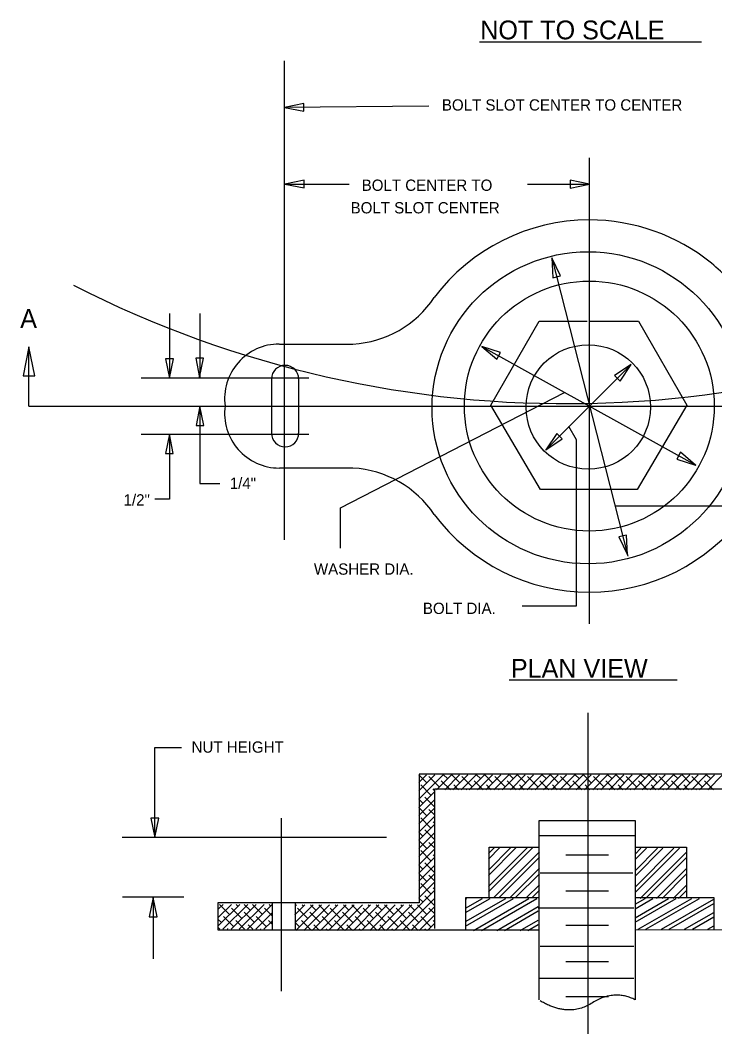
# Model space of a CAD drawing. Extents: x 12.4 to 19.6, y 6 to 16.1.
# Drawn here: x 12.93 to 16.63, y 10.72 to 16.11 of the extents above; entities that cross this region are included whole.
import ezdxf

# ---------------------------------------------------------------- set-up
doc = ezdxf.new("R2010")
doc.units = 0
for name, color, linetype in [('DETL-DIMS', 7, 'Continuous'), ('DETL-LINE', 7, 'Continuous'), ('DETL-NOTE', 7, 'Continuous'), ('DETL-PATT', 7, 'Continuous'), ('DETL-TITL', 7, 'Continuous')]:
    doc.layers.add(name, color=color, linetype=linetype)

msp = doc.modelspace()

# ---------------------------------------------------------------- linework, layer by layer
at = {"layer": 'DETL-DIMS'}
for p, q in [((14.3359, 13.3479), (14.3359, 15.8959)), ((14.3329, 15.6499), (15.1049, 15.6569)), ((15.9589, 12.9019), (15.9589, 15.3799)), ((14.3329, 15.2409), (14.6809, 15.2409)), ((15.6289, 15.2409), (15.9549, 15.2409)), ((15.7599, 14.8479), (16.1629, 13.2619)), ((13.7239, 14.5529), (13.7239, 14.2079)), ((13.8859, 14.5529), (13.8859, 14.2079)), ((15.3869, 14.3769), (16.5259, 13.7449)), ((15.7259, 13.8259), (16.1789, 14.2789)), ((14.4659, 14.2079), (13.5739, 14.2079)), ((14.6349, 13.5189), (15.8269, 14.1329)), ((13.8859, 14.0599), (13.8859, 13.6489)), ((15.8899, 13.8799), (15.8499, 13.9519)), ((14.4659, 13.9079), (13.5739, 13.9079)), ((13.7239, 13.9079), (13.7239, 13.5639)), ((15.8899, 12.9969), (15.8899, 13.8799)), ((13.8859, 13.6489), (13.9919, 13.6489)), ((13.7239, 13.5639), (13.6459, 13.5639)), ((14.6349, 13.3049), (14.6349, 13.5189)), ((16.9369, 13.5269), (16.0979, 13.5269)), ((15.6019, 12.9969), (15.8899, 12.9969)), ((15.9509, 12.4279), (15.9509, 10.7209)), ((13.6449, 12.2419), (13.6449, 11.7649)), ((13.7879, 12.2419), (13.6449, 12.2419)), ((14.3189, 11.8669), (14.3189, 10.9479)), ((14.8799, 11.7649), (13.4719, 11.7649)), ((13.8009, 11.4469), (13.4739, 11.4469)), ((13.6369, 11.4469), (13.6369, 11.1199))]:
    msp.add_line(p, q, dxfattribs=at)
for points in [[(14.3359, 15.6489), (14.4389, 15.6289), (14.4389, 15.6699)], [(14.3379, 15.2409), (14.4409, 15.2209), (14.4409, 15.2619)], [(15.9599, 15.2409), (15.8559, 15.2609), (15.8559, 15.2199)], [(15.7599, 14.8479), (15.7649, 14.7429), (15.8049, 14.7529)], [(12.9759, 14.3759), (12.9459, 14.2209), (13.0079, 14.2209)], [(15.3859, 14.3769), (15.4659, 14.3089), (15.4859, 14.3449)], [(13.7249, 14.2079), (13.7459, 14.3119), (13.7039, 14.3119)], [(13.8839, 14.2119), (13.9049, 14.3149), (13.8639, 14.3149)], [(16.1809, 14.2809), (16.0929, 14.2219), (16.1219, 14.1929)], [(13.8859, 14.0599), (13.8659, 13.9569), (13.9069, 13.9569)], [(15.7269, 13.8279), (15.8149, 13.8859), (15.7859, 13.9149)], [(13.7239, 13.9099), (13.7029, 13.8069), (13.7439, 13.8069)], [(16.5239, 13.7459), (16.4439, 13.8139), (16.4239, 13.7779)], [(16.1609, 13.2689), (16.1559, 13.3739), (16.1159, 13.3639)], [(13.6469, 11.7649), (13.6669, 11.8679), (13.6259, 11.8679)], [(13.6379, 11.4449), (13.6169, 11.3419), (13.6589, 11.3419)]]:
    msp.add_lwpolyline(points, close=True, dxfattribs=at)
for points in [[(12.9759, 14.0599), (12.9759, 14.3759)], [(12.9759, 14.0599), (18.9259, 14.0599)]]:
    msp.add_lwpolyline(points, dxfattribs=at)
msp.add_arc((15.8374, 19.8541), 5.7813, 243.01004, 299.38525, dxfattribs=at)
at = {"layer": 'DETL-LINE'}
for p, q in [((15.6919, 11.7759), (16.2069, 11.7759)), ((15.8329, 11.6729), (16.0599, 11.6729)), ((15.6969, 11.5769), (16.1899, 11.5769)), ((15.8329, 11.4809), (16.0599, 11.4809)), ((15.6859, 11.3899), (16.1959, 11.3899)), ((15.8329, 11.2989), (16.0599, 11.2989)), ((15.6969, 11.1859), (16.1959, 11.1859)), ((15.8329, 11.1059), (16.0599, 11.1059)), ((15.6919, 11.0159), (16.1959, 11.0159)), ((15.8329, 10.9189), (16.0599, 10.9189))]:
    msp.add_line(p, q, dxfattribs=at)
for points in [[(15.9639, 14.5109), (16.2209, 14.5109), (16.4769, 14.0649), (16.2129, 13.6169), (15.9559, 13.6169), (15.6979, 13.6169), (15.4349, 14.0649), (15.6909, 14.5109), (15.9479, 14.5109)], [(14.3089, 14.3899), (14.7009, 14.3899)], [(14.2679, 14.2049), (14.2679, 14.0599), (14.2679, 13.9159)], [(14.4119, 14.0599), (14.4119, 14.2049)], [(14.4119, 13.9159), (14.4119, 14.0599)], [(14.7009, 13.7299), (14.3089, 13.7299)], [(16.2019, 11.2739), (17.8999, 11.2749), (17.8999, 11.4279), (16.8679, 11.4279), (16.8679, 12.1019), (15.0529, 12.1019), (15.0529, 11.4179), (13.9819, 11.4179), (13.9809, 11.2729)], [(15.1359, 11.2799), (15.1359, 12.0229), (16.7859, 12.0229), (16.7859, 11.2799)], [(15.6919, 11.2709), (15.6919, 11.8549), (16.2019, 11.8549), (16.2019, 11.2709)], [(15.4249, 11.4449), (15.4249, 11.7129), (15.6899, 11.7129)], [(16.2079, 11.7129), (16.4759, 11.7129), (16.4759, 11.4449)], [(15.3009, 11.2739), (15.3009, 11.4449), (15.6899, 11.4449)], [(16.2079, 11.4449), (16.6209, 11.4449), (16.6209, 11.2739)], [(14.2699, 11.4179), (14.2699, 11.2729)], [(14.3929, 11.4179), (14.3929, 11.2729)], [(13.9809, 11.2729), (15.6919, 11.2739)], [(15.6919, 10.9019), (15.6919, 11.2769)], [(16.2019, 11.2709), (16.2019, 10.9019)]]:
    msp.add_lwpolyline(points, dxfattribs=at)
for centre, radius in [((15.952, 14.0508), 0.83), ((15.9586, 14.0601), 0.665), ((15.9532, 14.055), 0.3312)]:
    msp.add_circle(centre, radius, dxfattribs=at)
for centre, radius, start, end in [((15.9586, 14.0188), 1.0313, 90, 143.1301), ((15.9586, 14.0188), 1.0313, 50.9692, 90), ((15.9586, 14.0188), 1.0313, 36.8699, 50.9692), ((14.6692, 14.9475), 0.5583, 273.2108, 326.279), ((14.3086, 14.0987), 0.2913, 90, 187.6282), ((14.3395, 14.2044), 0.0722, 0, 180), ((14.3086, 14.0214), 0.2913, 172.3718, 270), ((14.3395, 13.9157), 0.0722, 180, 0), ((14.6692, 13.1726), 0.5583, 33.721, 86.7892), ((15.9586, 14.1013), 1.0313, 216.8699, 270), ((15.9586, 14.1013), 1.0313, 270, 323.1301)]:
    msp.add_arc(centre, radius, start, end, dxfattribs=at)
msp.add_open_spline([(16.2019, 10.9019), (16.0879, 10.9589), (15.8499, 10.8059), (15.6969, 10.8959)], degree=2, dxfattribs=at)
at = {"layer": 'DETL-PATT'}
for p, q in [((15.0509, 11.9689), (15.1809, 12.0989)), ((15.0509, 12.0129), (15.1369, 12.0989)), ((15.0509, 12.0569), (15.0929, 12.0989)), ((15.0939, 12.0559), (15.0519, 12.0989)), ((15.1599, 12.0339), (15.1049, 12.0889)), ((15.1449, 12.0189), (15.2249, 12.0989)), ((15.2039, 12.0779), (15.1829, 12.0989)), ((15.1889, 12.0189), (15.2679, 12.0989)), ((15.2689, 12.0559), (15.2269, 12.0989)), ((15.2329, 12.0189), (15.3119, 12.0989)), ((15.2759, 12.0189), (15.3559, 12.0989)), ((15.3349, 12.0339), (15.2799, 12.0889)), ((15.3199, 12.0189), (15.3999, 12.0989)), ((15.3789, 12.0779), (15.3579, 12.0989)), ((15.3639, 12.0189), (15.4429, 12.0989)), ((15.4439, 12.0559), (15.4019, 12.0989)), ((15.4079, 12.0189), (15.4869, 12.0989)), ((15.4509, 12.0189), (15.5309, 12.0989)), ((15.5099, 12.0339), (15.4549, 12.0889)), ((15.4949, 12.0189), (15.5749, 12.0989)), ((15.5539, 12.0779), (15.5329, 12.0989)), ((15.5389, 12.0189), (15.6179, 12.0989)), ((15.6189, 12.0559), (15.5769, 12.0989)), ((15.5829, 12.0189), (15.6619, 12.0989)), ((15.6269, 12.0189), (15.7059, 12.0989)), ((15.6849, 12.0339), (15.6299, 12.0889)), ((15.6699, 12.0189), (15.7499, 12.0989)), ((15.7289, 12.0779), (15.7079, 12.0989)), ((15.7139, 12.0189), (15.7929, 12.0989)), ((15.7939, 12.0559), (15.7519, 12.0989)), ((15.7579, 12.0189), (15.8369, 12.0989)), ((15.8019, 12.0189), (15.8809, 12.0989)), ((15.8599, 12.0339), (15.8049, 12.0889)), ((15.8449, 12.0189), (15.9249, 12.0989)), ((15.9039, 12.0779), (15.8829, 12.0989)), ((15.8889, 12.0189), (15.9679, 12.0989)), ((15.9689, 12.0559), (15.9269, 12.0989)), ((15.9329, 12.0189), (16.0119, 12.0989)), ((15.9769, 12.0189), (16.0559, 12.0989)), ((16.0349, 12.0339), (15.9799, 12.0889)), ((16.0199, 12.0189), (16.0999, 12.0989)), ((16.0789, 12.0779), (16.0579, 12.0989)), ((16.0639, 12.0189), (16.1429, 12.0989)), ((16.1439, 12.0559), (16.1019, 12.0989)), ((16.1079, 12.0189), (16.1869, 12.0989)), ((16.1519, 12.0189), (16.2309, 12.0989)), ((16.2099, 12.0339), (16.1549, 12.0889)), ((16.1949, 12.0189), (16.2749, 12.0989)), ((16.2539, 12.0779), (16.2329, 12.0989)), ((16.2389, 12.0189), (16.3179, 12.0989)), ((16.3189, 12.0559), (16.2769, 12.0989)), ((16.2829, 12.0189), (16.3619, 12.0989)), ((16.3269, 12.0189), (16.4059, 12.0989)), ((16.3849, 12.0339), (16.3299, 12.0889)), ((16.3699, 12.0189), (16.4499, 12.0989)), ((16.4289, 12.0779), (16.4079, 12.0989)), ((16.4139, 12.0189), (16.4929, 12.0989)), ((16.4939, 12.0559), (16.4519, 12.0989)), ((16.4579, 12.0189), (16.5369, 12.0989)), ((16.5019, 12.0189), (16.5809, 12.0989)), ((16.5599, 12.0339), (16.5049, 12.0889)), ((16.5449, 12.0189), (16.6249, 12.0989)), ((16.6039, 12.0779), (16.5829, 12.0989)), ((16.5889, 12.0189), (16.6679, 12.0989)), ((15.1159, 11.9899), (15.0619, 12.0449)), ((15.2189, 12.0189), (15.1709, 12.0669)), ((15.2619, 12.0189), (15.2369, 12.0449)), ((15.3939, 12.0189), (15.3459, 12.0669)), ((15.4369, 12.0189), (15.4119, 12.0449)), ((15.5689, 12.0189), (15.5209, 12.0669)), ((15.6119, 12.0189), (15.5869, 12.0449)), ((15.7439, 12.0189), (15.6959, 12.0669)), ((15.7869, 12.0189), (15.7619, 12.0449)), ((15.9189, 12.0189), (15.8709, 12.0669)), ((15.9619, 12.0189), (15.9369, 12.0449)), ((16.0939, 12.0189), (16.0459, 12.0669)), ((16.1369, 12.0189), (16.1119, 12.0449)), ((16.2689, 12.0189), (16.2209, 12.0669)), ((16.3119, 12.0189), (16.2869, 12.0449)), ((16.4439, 12.0189), (16.3959, 12.0669)), ((16.4869, 12.0189), (16.4619, 12.0449)), ((16.6189, 12.0189), (16.5709, 12.0669)), ((15.0509, 11.9249), (15.1359, 12.0099)), ((15.1359, 11.9269), (15.0829, 11.9799)), ((15.1359, 12.0139), (15.1269, 12.0229)), ((15.3059, 12.0189), (15.3019, 12.0229)), ((15.4809, 12.0189), (15.4769, 12.0229)), ((15.6559, 12.0189), (15.6519, 12.0229)), ((15.8309, 12.0189), (15.8269, 12.0229)), ((16.0059, 12.0189), (16.0019, 12.0229)), ((16.1809, 12.0189), (16.1769, 12.0229)), ((16.3559, 12.0189), (16.3519, 12.0229)), ((16.5309, 12.0189), (16.5269, 12.0229)), ((15.0719, 11.9469), (15.0509, 11.9679)), ((15.0509, 11.8819), (15.1359, 11.9669)), ((15.0939, 11.8809), (15.0509, 11.9239)), ((15.0509, 11.8379), (15.1359, 11.9229)), ((15.0509, 11.7939), (15.1359, 11.8789)), ((15.1159, 11.8149), (15.0619, 11.8699)), ((15.1359, 11.8829), (15.1049, 11.9139)), ((15.0509, 11.7499), (15.1359, 11.8349)), ((15.1359, 11.8389), (15.1269, 11.8479)), ((15.0719, 11.7719), (15.0509, 11.7929)), ((15.0509, 11.7069), (15.1359, 11.7919)), ((15.1359, 11.7519), (15.0829, 11.8049)), ((15.0939, 11.7059), (15.0509, 11.7489)), ((15.0509, 11.6629), (15.1359, 11.7479)), ((15.0509, 11.6189), (15.1359, 11.7039)), ((15.1359, 11.7079), (15.1049, 11.7389)), ((15.4219, 11.5039), (15.6289, 11.7119)), ((15.4219, 11.5919), (15.5409, 11.7119)), ((15.4219, 11.6799), (15.4539, 11.7119)), ((15.4219, 11.4749), (15.6579, 11.7119)), ((15.4219, 11.5629), (15.5699, 11.7119)), ((15.4219, 11.6499), (15.4829, 11.7119)), ((16.2019, 11.5009), (16.4079, 11.7079)), ((16.2019, 11.5879), (16.3209, 11.7079)), ((16.2019, 11.6759), (16.2329, 11.7079)), ((16.2019, 11.4719), (16.4379, 11.7079)), ((16.2019, 11.5589), (16.3499, 11.7079)), ((16.2019, 11.6469), (16.2629, 11.7079)), ((15.0509, 11.5749), (15.1359, 11.6599)), ((15.1159, 11.6399), (15.0619, 11.6949)), ((15.1359, 11.6639), (15.1269, 11.6729)), ((15.4499, 11.4449), (15.6939, 11.6889)), ((15.4789, 11.4449), (15.6939, 11.6599)), ((16.2289, 11.4409), (16.4739, 11.6849)), ((16.2579, 11.4409), (16.4739, 11.6559)), ((15.0719, 11.5969), (15.0509, 11.6179)), ((15.0509, 11.5319), (15.1359, 11.6169)), ((15.1359, 11.5769), (15.0829, 11.6299)), ((15.5369, 11.4449), (15.6939, 11.6019)), ((16.3169, 11.4409), (16.4739, 11.5979)), ((15.0939, 11.5309), (15.0509, 11.5739)), ((15.0509, 11.4879), (15.1359, 11.5729)), ((15.1359, 11.5329), (15.1049, 11.5639)), ((15.5659, 11.4449), (15.6939, 11.5719)), ((16.3459, 11.4409), (16.4739, 11.5689)), ((14.9219, 11.2709), (15.1359, 11.4849)), ((15.0509, 11.4439), (15.1359, 11.5289)), ((15.1159, 11.4649), (15.0619, 11.5199)), ((15.1359, 11.4889), (15.1269, 11.4979)), ((15.6249, 11.4449), (15.6939, 11.5139)), ((15.6539, 11.4449), (15.6939, 11.4849)), ((16.4039, 11.4409), (16.4739, 11.5099)), ((14.9649, 11.2709), (15.1359, 11.4419)), ((15.0719, 11.4219), (15.0509, 11.4429)), ((15.1359, 11.4019), (15.0829, 11.4549)), ((15.2999, 11.3179), (15.5139, 11.4409)), ((15.2999, 11.3889), (15.3899, 11.4409)), ((15.2999, 11.2939), (15.5549, 11.4409)), ((15.2999, 11.3659), (15.4309, 11.4409)), ((15.2999, 11.4369), (15.3069, 11.4409)), ((15.3429, 11.2709), (15.6369, 11.4409)), ((15.3839, 11.2709), (15.6789, 11.4409)), ((16.2019, 11.3379), (16.3799, 11.4409)), ((16.2019, 11.4099), (16.2559, 11.4409)), ((16.2019, 11.3139), (16.4209, 11.4409)), ((16.2019, 11.3859), (16.2969, 11.4409)), ((16.2189, 11.2769), (16.5039, 11.4409)), ((16.2599, 11.2769), (16.5449, 11.4409)), ((16.3419, 11.2769), (16.6209, 11.4369)), ((16.4339, 11.4409), (16.4739, 11.4809)), ((13.9839, 11.2949), (14.0979, 11.4089)), ((13.9839, 11.3389), (14.0539, 11.4089)), ((13.9839, 11.3829), (14.0099, 11.4089)), ((14.0439, 11.3559), (13.9909, 11.4089)), ((14.0089, 11.2769), (14.1409, 11.4089)), ((14.0519, 11.2769), (14.1849, 11.4089)), ((14.1099, 11.3339), (14.0549, 11.3889)), ((14.0879, 11.3999), (14.0789, 11.4089)), ((14.0959, 11.2769), (14.2289, 11.4089)), ((14.1539, 11.3779), (14.1219, 11.4089)), ((14.1399, 11.2769), (14.2689, 11.4059)), ((14.2189, 11.3559), (14.1659, 11.4089)), ((14.2689, 11.3499), (14.2299, 11.3889)), ((14.2629, 11.3999), (14.2539, 11.4089)), ((14.3939, 11.3119), (14.4889, 11.4069)), ((14.3939, 11.3549), (14.4449, 11.4069)), ((14.3939, 11.3989), (14.4009, 11.4069)), ((14.3969, 11.2709), (14.5329, 11.4069)), ((14.4599, 11.3339), (14.4049, 11.3889)), ((14.4379, 11.3999), (14.4309, 11.4069)), ((14.4399, 11.2709), (14.5759, 11.4069)), ((14.5039, 11.3779), (14.4749, 11.4069)), ((14.4839, 11.2709), (14.6199, 11.4069)), ((14.5689, 11.3559), (14.5189, 11.4069)), ((14.5279, 11.2709), (14.6639, 11.4069)), ((14.5709, 11.2709), (14.7079, 11.4069)), ((14.6349, 11.3339), (14.5799, 11.3889)), ((14.6129, 11.3999), (14.6059, 11.4069)), ((14.6149, 11.2709), (14.7509, 11.4069)), ((14.6789, 11.3779), (14.6499, 11.4069)), ((14.6589, 11.2709), (14.7949, 11.4069)), ((14.7439, 11.3559), (14.6939, 11.4069)), ((14.7029, 11.2709), (14.8389, 11.4069)), ((14.7469, 11.2709), (14.8829, 11.4069)), ((14.8099, 11.3339), (14.7549, 11.3889)), ((14.7879, 11.3999), (14.7809, 11.4069)), ((14.7899, 11.2709), (14.9259, 11.4069)), ((14.8539, 11.3779), (14.8249, 11.4069)), ((14.8339, 11.2709), (14.9699, 11.4069)), ((14.9189, 11.3559), (14.8679, 11.4069)), ((14.8779, 11.2709), (15.0139, 11.4069)), ((14.9849, 11.3339), (14.9299, 11.3889)), ((14.9629, 11.3999), (14.9559, 11.4069)), ((15.0289, 11.3779), (14.9999, 11.4069)), ((15.0089, 11.2709), (15.1359, 11.3979)), ((15.0939, 11.3559), (15.0439, 11.4069)), ((15.1359, 11.3579), (15.1049, 11.3889)), ((15.4659, 11.2709), (15.6859, 11.3979)), ((16.3839, 11.2769), (16.6209, 11.4139)), ((14.0009, 11.3119), (13.9839, 11.3289)), ((14.0659, 11.2899), (14.0109, 11.3449)), ((14.1239, 11.2769), (14.0769, 11.3229)), ((14.1759, 11.3119), (14.1209, 11.3669)), ((14.1839, 11.2769), (14.2689, 11.3619)), ((14.2409, 11.2899), (14.1859, 11.3449)), ((14.2689, 11.3059), (14.2519, 11.3229)), ((14.3939, 11.3559), (14.3939, 11.3569)), ((14.4799, 11.2709), (14.4269, 11.3229)), ((14.5259, 11.3119), (14.4709, 11.3669)), ((14.5909, 11.2899), (14.5369, 11.3449)), ((14.6549, 11.2709), (14.6019, 11.3229)), ((14.7009, 11.3119), (14.6459, 11.3669)), ((14.7659, 11.2899), (14.7119, 11.3449)), ((14.8299, 11.2709), (14.7769, 11.3229)), ((14.8759, 11.3119), (14.8209, 11.3669)), ((14.9409, 11.2899), (14.8869, 11.3449)), ((15.0049, 11.2709), (14.9519, 11.3229)), ((15.0509, 11.3119), (14.9959, 11.3669)), ((15.0529, 11.2709), (15.1359, 11.3539)), ((15.1159, 11.2899), (15.0619, 11.3449)), ((15.1359, 11.3139), (15.1269, 11.3229)), ((15.5079, 11.2709), (15.6859, 11.3739)), ((15.5899, 11.2709), (15.6859, 11.3259)), ((16.4659, 11.2769), (16.6209, 11.3659)), ((16.5069, 11.2769), (16.6209, 11.3419)), ((13.9919, 11.2769), (13.9839, 11.2859)), ((14.0359, 11.2769), (14.0329, 11.2789)), ((14.1679, 11.2769), (14.1429, 11.3009)), ((14.2109, 11.2769), (14.2079, 11.2789)), ((14.2269, 11.2769), (14.2689, 11.3179)), ((14.4159, 11.2899), (14.3939, 11.3129)), ((14.5229, 11.2709), (14.4929, 11.3009)), ((14.5669, 11.2709), (14.5579, 11.2789)), ((14.6979, 11.2709), (14.6679, 11.3009)), ((14.7419, 11.2709), (14.7329, 11.2789)), ((14.8729, 11.2709), (14.8429, 11.3009)), ((14.9169, 11.2709), (14.9079, 11.2789)), ((15.0479, 11.2709), (15.0179, 11.3009)), ((15.0919, 11.2709), (15.0829, 11.2789)), ((15.0969, 11.2709), (15.1359, 11.3099)), ((15.6309, 11.2709), (15.6859, 11.3019)), ((16.5899, 11.2769), (16.6209, 11.2949))]:
    msp.add_line(p, q, dxfattribs=at)
at = {"layer": 'DETL-TITL'}
for p, q in [((15.3737, 15.9984), (16.5563, 15.9984)), ((15.532, 12.6028), (16.4259, 12.6028))]:
    msp.add_line(p, q, dxfattribs=at)

# ---------------------------------------------------------------- texts
at = {"layer": 'DETL-NOTE'}
for s, height, p in [('BOLT SLOT CENTER TO CENTER', 0.06, (15.1739, 15.6319)), ('BOLT CENTER TO', 0.06, (14.7471, 15.2049)), ('BOLT SLOT CENTER', 0.06, (14.6882, 15.0849)), ('A', 0.1, (12.9299, 14.4759)), ('1/4"', 0.06, (14.0449, 13.6189)), ('1/2"', 0.06, (13.4799, 13.5309)), ('WASHER DIA.', 0.06, (14.4929, 13.1629)), ('BOLT DIA.', 0.06, (15.0729, 12.9539)), ('NUT HEIGHT', 0.06, (13.8419, 12.2159))]:
    msp.add_text(s, height=height, dxfattribs=at).set_placement(p)
at = {"layer": 'DETL-TITL'}
for s, height, p in [('NOT TO SCALE', 0.100002, (15.3779, 16.0109)), ('PLAN VIEW', 0.1, (15.5409, 12.6149))]:
    msp.add_text(s, height=height, dxfattribs=at).set_placement(p)

doc.saveas('drawing.dxf')
